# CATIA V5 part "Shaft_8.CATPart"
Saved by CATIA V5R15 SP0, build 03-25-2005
Part number: Shaft_8
Bounding box of the stored display mesh (mm): x -23.8 to 23.8, y -23.8 to 23.8, z 0 to 632
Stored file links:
  E:\#01 CATIA Lecture Materials\#06 DMU\#11 DMU Page01 KIN EX11\Shaft_8.CATPart
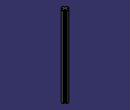
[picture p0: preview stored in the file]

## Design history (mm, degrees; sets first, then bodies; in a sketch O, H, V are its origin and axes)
Body1 (main body)
  Sketch1 on xy-plane, origin (0, 0, 0), H (1, 0, 0), V (0, 1, 0)
    arc A1 centre (0, 0) radius 23.8 from (21.9289, -9.25) to (21.9289, 9.25) ccw
    line L1 (-21.9289, 9.25) -> (-9.25, 9.25)
    line L2 (21.9289, -9.25) -> (9.25, -9.25)
    line L3 (9.25, 21.9289) -> (9.25, 9.25)
    line L4 (-9.25, -21.9289) -> (-9.25, -9.25)
    point P4 (-9.25, -21.9289)
    arc A2 centre (0, 0) radius 23.8 from (-9.25, -21.9289) to (9.25, -21.9289) ccw
    point P6 (-21.9289, 9.25)
    arc A3 centre (0, 0) radius 23.8 from (-21.9289, 9.25) to (-21.9289, -9.25) ccw
    point P8 (9.25, 21.9289)
    arc A4 centre (0, 0) radius 23.8 from (9.25, 21.9289) to (-9.25, 21.9289) ccw
    point P9 (-9.25, 9.25)
    line L5 (9.25, 9.25) -> (21.9289, 9.25)
    line L6 (9.25, -9.25) -> (9.25, -21.9289)
    line L7 (-9.25, 9.25) -> (-9.25, 21.9289)
    point P12 (-9.25, -9.25)
    line L8 (-9.25, -9.25) -> (-21.9289, -9.25)
    radius A1 = 23.8
    distance L1 L2 = 18.5
    distance H L1 = 9.25
    distance L3 L4 = 18.5
    distance V L3 = 9.25
    horizontal: L1 H, L2 H, L5 H, L8 H
    vertical: L3 V, L4 V, L6 V, L7 V
    coincidence: A1 P4, A1 A2, A1 P6, A1 A3, A1 P8, A1 A4, L4 P9, L1 L5, L3 L6, L2 P12, L4 L7, L2 L8
  Pad1: profile Sketch1, direction (0, 0, 1), length 632
  Fillet1: radius 2, on edge [face of Pad1 | face of Pad1] (x4)
  Fillet2: radius 2, on face of Pad1 (x2)
  Fillet3: radius 2, on edge [face of Pad1 from Sketch1.A4 | face of Pad1 from Sketch1.L3]; edge [face of Pad1 from Sketch1.L5 | face of Pad1 from Sketch1.A1]; edge [face of Pad1 from Sketch1.L7 | face of Pad1 from Sketch1.A4]; edge [face of Pad1 from Sketch1.A1 | face of Pad1 from Sketch1.L2]; edge [face of Pad1 from Sketch1.L6 | face of Pad1 from Sketch1.A2]; edge [face of Pad1 from Sketch1.A2 | face of Pad1 from Sketch1.L4]; edge [face of Pad1 from Sketch1.L8 | face of Pad1 from Sketch1.A3]; edge [face of Pad1 from Sketch1.A3 | face of Pad1 from Sketch1.L1]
